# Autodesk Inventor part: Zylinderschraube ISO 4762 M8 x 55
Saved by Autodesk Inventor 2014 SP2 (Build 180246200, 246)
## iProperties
Created: 2015-07
Part Number: Zylinderschraube ISO 4762 M8 x 55
Material: Generisch
Document SubType Name: Modeling
Designer: e_krauts
Density: 1 g/cm^3
Appearance: Vorgabe
Mass: 3.67451 g
Surface Area: 20.4135 cm^2
Volume: 3.67451 cm^3
Sending System: SolidWorks 2011
Last Author: e_boekem
Sachnummer: ISO 4762 M8x55
Einheit: Stck.
Author: e_krauts
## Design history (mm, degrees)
node "Zylinderschraube ISO 4762 M8 x 55.ipt1"
node "Hex"
node "Basis1"
